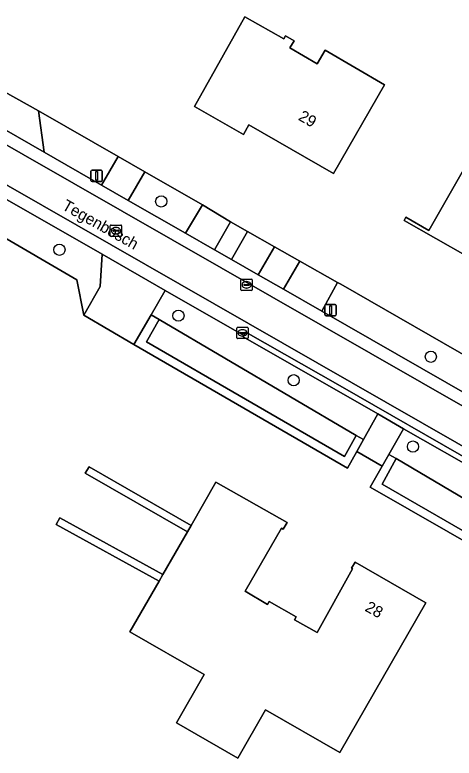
# Model space of a CAD drawing. Extents: x 156502 to 159075, y 384229 to 386100.
# Drawn here: x 157102.6 to 157141.1, y 385699.9 to 385765 of the extents above; entities that cross this region are included whole.
import ezdxf

# ---------------------------------------------------------------- set-up
doc = ezdxf.new("R2010")
doc.units = 0
for name, color, linetype in [('IMGEO_Berm_groen', 7, 'Continuous'), ('IMGEO_Berm_open', 7, 'Continuous'), ('IMGEO_Boom', 7, 'Continuous'), ('IMGEO_Brandkraan', 7, 'Continuous'), ('IMGEO_Erf', 7, 'Continuous'), ('IMGEO_Groenvoorziening', 7, 'Continuous'), ('IMGEO_Hek', 7, 'Continuous'), ('IMGEO_Kolk', 7, 'Continuous'), ('IMGEO_Lichtmast', 7, 'Continuous'), ('IMGEO_Muur', 7, 'Continuous'), ('IMGEO_Openbare_ruimte_label', 7, 'Continuous'), ('IMGEO_Pand', 7, 'Continuous'), ('IMGEO_Pand_nummerreeks', 7, 'Continuous'), ('IMGEO_Rijbaan_lokaal_gesloten', 7, 'Continuous'), ('IMGEO_Rijbaan_lokaal_halfverhard', 7, 'Continuous'), ('IMGEO_Rijbaan_lokaal_open', 7, 'Continuous'), ('IMGEO_Rioolput', 7, 'Continuous'), ('IMGEO_Voetpad_open', 7, 'Continuous')]:
    doc.layers.add(name, color=color, linetype=linetype)

msp = doc.modelspace()

# ---------------------------------------------------------------- linework, layer by layer
at = {"layer": 'IMGEO_Berm_groen'}
for points in [[(157109.515, 385753.847), (157104.7, 385756.591), (157105.201, 385752.99), (157110.239, 385750.099), (157111.678, 385752.607)], [(157114.022, 385751.264), (157112.582, 385748.755), (157117.587, 385745.884), (157119.086, 385748.362)], [(157123.015, 385746.039), (157121.522, 385746.887), (157120.125, 385744.429), (157121.61, 385743.581)], [(157127.595, 385743.439), (157125.376, 385744.699), (157123.969, 385742.234), (157126.176, 385740.973)], [(157131.197, 385741.421), (157130.921, 385741.579), (157129.529, 385739.04), (157142.675, 385731.515), (157144.11, 385733.995)], [(157122.629, 385736.809), (157122.692, 385736.917), (157115.815, 385740.863), (157114.588, 385738.742), (157115.289, 385738.328), (157132.534, 385728.173), (157133.189, 385727.815), (157134.443, 385730.048)]]:
    msp.add_lwpolyline(points, close=True, dxfattribs=at)
at = {"layer": 'IMGEO_Berm_open'}
for points in [[(157151.556, 385720.809), (157143.135, 385725.639), (157131.139, 385732.504), (157122.862, 385737.211), (157122.692, 385736.917)], [(157122.692, 385736.917), (157122.629, 385736.809), (157134.443, 385730.048), (157136.699, 385728.757), (157143.67, 385724.768), (157152.438, 385719.741)]]:
    msp.add_lwpolyline(points, dxfattribs=at)
at = {"layer": 'IMGEO_Boom'}
for centre in [(157115.464, 385748.663), (157106.548, 385744.43), (157116.973, 385738.659), (157139.084, 385735.062), (157127.07, 385733.005), (157137.513, 385727.198)]:
    msp.add_circle(centre, 0.489, dxfattribs=at)
at = {"layer": 'IMGEO_Brandkraan'}
for p, q in [((157110.997, 385745.674), (157110.997, 385746.526)), ((157111.072, 385746.6), (157111.924, 385746.6)), ((157111.256, 385746.094), (157111.256, 385746.106)), ((157111.299, 385746.143), (157111.697, 385746.143)), ((157111.485, 385746.38), (157111.51, 385746.38)), ((157111.74, 385746.106), (157111.74, 385746.094)), ((157111.998, 385746.526), (157111.998, 385745.674)), ((157111.924, 385745.6), (157111.072, 385745.6)), ((157111.694, 385746.057), (157111.296, 385746.057)), ((157111.508, 385745.82), (157111.483, 385745.82))]:
    msp.add_line(p, q, dxfattribs=at)
for points in [[(157110.997, 385745.674), (157110.997, 385746.526)], [(157111.072, 385746.6), (157111.924, 385746.6)], [(157111.998, 385746.526), (157111.998, 385745.674)], [(157111.924, 385745.6), (157111.072, 385745.6)]]:
    msp.add_lwpolyline(points, dxfattribs=at)
for centre, radius, start, end in [((157111.074, 385746.524), 0.0765, 91.55205, 178.44795), ((157111.074, 385746.524), 0.0765, 91.55205, 178.44795), ((157111.296, 385746.103), 0.0403, 85.87752, 175.75265), ((157111.293, 385746.093), 0.0366, 178.93798, 274.71019), ((157111.697, 385746.1), 0.043, 264.86636, 352.45326), ((157111.701, 385746.105), 0.0386, 1.73085, 96.63898), ((157111.922, 385746.524), 0.0765, 1.55205, 88.44795), ((157111.922, 385746.524), 0.0765, 1.55205, 88.44795), ((157111.074, 385745.676), 0.0765, 181.55205, 268.44795), ((157111.074, 385745.676), 0.0765, 181.55205, 268.44795), ((157111.922, 385745.676), 0.0765, 271.55205, 358.44795), ((157111.922, 385745.676), 0.0765, 271.55205, 358.44795)]:
    msp.add_arc(centre, radius, start, end, dxfattribs=at)
for centre, major_axis, ratio, start_param, end_param in [((157111.484, 385746.1), (-0.387, 0.002), 0.722429, 4.712389, 7.853982), ((157111.509, 385746.1), (-0.39, 0.002), 0.717154, 1.570796, 4.712389)]:
    msp.add_ellipse(centre, major_axis=major_axis, ratio=ratio, start_param=start_param, end_param=end_param, dxfattribs=at)
at = {"layer": 'IMGEO_Erf'}
for points in [[(157048.701, 385788.533), (157057.714, 385783.415), (157062.278, 385780.824), (157070.393, 385776.216), (157073.942, 385774.201), (157084.266, 385768.252), (157086.152, 385767.162), (157101.744, 385758.276), (157104.7, 385756.591), (157109.515, 385753.847), (157111.678, 385752.607), (157114.022, 385751.264), (157119.086, 385748.362), (157121.522, 385746.887), (157123.015, 385746.039), (157125.376, 385744.699), (157127.595, 385743.439), (157130.921, 385741.579), (157131.197, 385741.421), (157144.11, 385733.995)], [(157147.432, 385715.812), (157133.773, 385723.654), (157134.821, 385725.475), (157132.597, 385726.756), (157131.792, 385725.315), (157113.077, 385736.144), (157108.687, 385738.705), (157108.063, 385741.81), (157080.131, 385758.103), (157080.304, 385758.402), (157074.239, 385761.861), (157074.046, 385761.597), (157054.491, 385772.88), (157047.62, 385771.736)], [(157155.054, 385714.92), (157136.059, 385726.15), (157134.817, 385723.916), (157148.149, 385716.222)]]:
    msp.add_lwpolyline(points, dxfattribs=at)
for points in [[(157135.024, 385758.88), (157130.566, 385751.114), (157123.153, 385755.388), (157122.659, 385754.53), (157118.377, 385756.989), (157122.783, 385764.825), (157126.205, 385762.901), (157126.359, 385763.168), (157127.097, 385762.742), (157126.732, 385762.11), (157129.127, 385760.725), (157129.832, 385761.927)], [(157145.011, 385756.807), (157153.044, 385752.202), (157152.682, 385751.64), (157154.769, 385750.435), (157156.174, 385752.869), (157159.745, 385750.827), (157155.568, 385743.525), (157151.995, 385745.568), (157152.803, 385746.981), (157150.715, 385748.193), (157146.759, 385741.271), (157143.69, 385743.027), (157143.418, 385742.572), (157142.025, 385743.36), (157142.291, 385743.83), (157136.743, 385747.004), (157136.902, 385747.281), (157138.903, 385746.106)], [(157118.085, 385720.296), (157120.262, 385724.082), (157126.486, 385720.538), (157126.139, 385719.951), (157125.993, 385720.037), (157122.807, 385714.519), (157124.768, 385713.361), (157124.932, 385713.638), (157127.284, 385712.292), (157127.135, 385712.031), (157129.124, 385710.909), (157132.229, 385716.487), (157132.142, 385716.536), (157132.448, 385717.077), (157138.641, 385713.517), (157131.101, 385700.4), (157124.599, 385704.138), (157122.166, 385699.907), (157116.791, 385702.997), (157119.223, 385707.228), (157112.721, 385710.965), (157115.281, 385715.419), (157106.27, 385720.374), (157106.584, 385720.945), (157115.606, 385715.984), (157117.757, 385719.726), (157108.815, 385724.856), (157109.142, 385725.426)]]:
    msp.add_lwpolyline(points, close=True, dxfattribs=at)
at = {"layer": 'IMGEO_Groenvoorziening'}
for points in [[(157081.499, 385760.496), (157080.304, 385758.402), (157080.131, 385758.103), (157108.063, 385741.81), (157108.687, 385738.705), (157110.125, 385741.217), (157110.277, 385744.036)], [(157115.289, 385738.328), (157114.177, 385736.375), (157131.533, 385726.329), (157132.534, 385728.173)]]:
    msp.add_lwpolyline(points, close=True, dxfattribs=at)
msp.add_lwpolyline([(157152.438, 385719.741), (157143.67, 385724.768), (157136.699, 385728.757), (157135.417, 385726.51), (157136.059, 385726.15), (157155.054, 385714.92), (157165.17, 385704.25), (157165.011, 385703.658), (157167.069, 385705.548), (157167.262, 385706.33), (157166.599, 385707.057), (157163.676, 385710.253), (157162.212, 385711.565), (157160.802, 385712.985)], dxfattribs=at)
at = {"layer": 'IMGEO_Hek'}
for points in [[(157108.687, 385738.705), (157108.063, 385741.81), (157080.131, 385758.103)], [(157101.744, 385758.276), (157104.7, 385756.591)], [(157104.7, 385756.591), (157109.515, 385753.847)], [(157131.197, 385741.421), (157144.11, 385733.995)]]:
    msp.add_lwpolyline(points, dxfattribs=at)
at = {"layer": 'IMGEO_Kolk'}
for p, q in [((157122.16, 385737.652), (157123.012, 385737.652)), ((157122.085, 385736.726), (157122.085, 385737.578)), ((157122.344, 385737.146), (157122.344, 385737.158)), ((157122.782, 385737.109), (157122.384, 385737.109)), ((157122.387, 385737.195), (157122.785, 385737.195)), ((157122.573, 385737.432), (157122.598, 385737.432)), ((157122.828, 385737.158), (157122.828, 385737.146)), ((157123.086, 385737.578), (157123.086, 385736.726)), ((157123.012, 385736.652), (157122.16, 385736.652)), ((157122.596, 385736.872), (157122.571, 385736.872))]:
    msp.add_line(p, q, dxfattribs=at)
for points in [[(157122.16, 385737.652), (157123.012, 385737.652)], [(157122.085, 385736.726), (157122.085, 385737.578)], [(157123.086, 385737.578), (157123.086, 385736.726)], [(157123.012, 385736.652), (157122.16, 385736.652)]]:
    msp.add_lwpolyline(points, dxfattribs=at)
for centre, radius, start, end in [((157122.162, 385737.576), 0.0765, 91.55205, 178.44795), ((157122.162, 385737.576), 0.0765, 91.55205, 178.44795), ((157123.01, 385737.576), 0.0765, 1.55205, 88.44795), ((157123.01, 385737.576), 0.0765, 1.55205, 88.44795), ((157122.384, 385737.155), 0.0403, 85.87752, 175.75265), ((157122.381, 385737.145), 0.0366, 178.93798, 274.71019), ((157122.785, 385737.152), 0.043, 264.86636, 352.45326), ((157122.789, 385737.157), 0.0386, 1.73085, 96.63898), ((157122.162, 385736.728), 0.0765, 181.55205, 268.44795), ((157122.162, 385736.728), 0.0765, 181.55205, 268.44795), ((157123.01, 385736.728), 0.0765, 271.55205, 358.44795), ((157123.01, 385736.728), 0.0765, 271.55205, 358.44795)]:
    msp.add_arc(centre, radius, start, end, dxfattribs=at)
for centre, major_axis, ratio, start_param, end_param in [((157122.572, 385737.152), (-0.387, 0.002), 0.722429, 4.712389, 7.853982), ((157122.597, 385737.152), (-0.39, 0.002), 0.717154, 1.570796, 4.712389)]:
    msp.add_ellipse(centre, major_axis=major_axis, ratio=ratio, start_param=start_param, end_param=end_param, dxfattribs=at)
at = {"layer": 'IMGEO_Lichtmast'}
for p, q in [((157109.31, 385750.506), (157109.31, 385751.306)), ((157109.31, 385751.306), (157109.31, 385750.506)), ((157109.41, 385751.406), (157110.2, 385751.406)), ((157110.2, 385751.406), (157109.41, 385751.406)), ((157110.3, 385751.306), (157110.3, 385750.506)), ((157110.3, 385750.506), (157110.3, 385751.306)), ((157110.2, 385750.406), (157109.41, 385750.406)), ((157109.41, 385750.406), (157110.2, 385750.406)), ((157129.909, 385739.652), (157130.699, 385739.652)), ((157130.699, 385739.652), (157129.909, 385739.652)), ((157129.809, 385738.752), (157129.809, 385739.552)), ((157129.809, 385739.552), (157129.809, 385738.752)), ((157130.799, 385739.552), (157130.799, 385738.752)), ((157130.799, 385738.752), (157130.799, 385739.552)), ((157130.699, 385738.652), (157129.909, 385738.652)), ((157129.909, 385738.652), (157130.699, 385738.652))]:
    msp.add_line(p, q, dxfattribs=at)
for points in [[(157109.73, 385751.281), (157109.88, 385751.281), (157109.88, 385750.531), (157109.73, 385750.531), (157109.73, 385751.281)], [(157130.229, 385739.527), (157130.379, 385739.527), (157130.379, 385738.777), (157130.229, 385738.777), (157130.229, 385739.527)]]:
    msp.add_lwpolyline(points, dxfattribs=at)
for centre, start, end in [((157109.41, 385751.306), 90, 180), ((157109.41, 385751.306), 90, 180), ((157110.2, 385751.306), 0, 90), ((157110.2, 385751.306), 360, 90), ((157109.41, 385750.506), 180, 270), ((157109.41, 385750.506), 180, 270), ((157110.2, 385750.506), 270, 0), ((157110.2, 385750.506), 270, 0), ((157129.909, 385739.552), 90, 180), ((157129.909, 385739.552), 90, 180), ((157130.699, 385739.552), 0, 90), ((157130.699, 385739.552), 360, 90), ((157129.909, 385738.752), 180, 270), ((157129.909, 385738.752), 180, 270), ((157130.699, 385738.752), 270, 0), ((157130.699, 385738.752), 270, 0)]:
    msp.add_arc(centre, 0.1, start, end, dxfattribs=at)
at = {"layer": 'IMGEO_Muur'}
for points in [[(157133.189, 385727.815), (157132.534, 385728.173), (157131.533, 385726.329), (157114.177, 385736.375), (157115.289, 385738.328), (157114.588, 385738.742), (157113.077, 385736.144), (157131.792, 385725.315), (157132.597, 385726.756)], [(157148.362, 385711.898), (157148.149, 385716.222), (157134.817, 385723.916), (157136.059, 385726.15), (157135.417, 385726.51), (157134.821, 385725.475), (157133.773, 385723.654), (157147.432, 385715.812), (157147.812, 385707.892), (157148.558, 385707.925)], [(157118.085, 385720.296), (157109.142, 385725.426), (157108.815, 385724.856), (157117.757, 385719.726)], [(157115.606, 385715.984), (157106.584, 385720.945), (157106.27, 385720.374), (157115.281, 385715.419)]]:
    msp.add_lwpolyline(points, close=True, dxfattribs=at)
at = {"layer": 'IMGEO_Pand'}
for points in [[(157130.566, 385751.114), (157135.024, 385758.88), (157129.832, 385761.927), (157129.127, 385760.725), (157126.732, 385762.11), (157127.097, 385762.742), (157126.359, 385763.168), (157126.205, 385762.901), (157122.783, 385764.825), (157118.377, 385756.989), (157122.659, 385754.53), (157123.153, 385755.388)], [(157146.759, 385741.271), (157150.715, 385748.193), (157152.803, 385746.981), (157151.995, 385745.568), (157155.568, 385743.525), (157159.745, 385750.827), (157156.174, 385752.869), (157154.769, 385750.435), (157152.682, 385751.64), (157153.044, 385752.202), (157145.011, 385756.807), (157138.903, 385746.106), (157136.902, 385747.281), (157136.743, 385747.004), (157142.291, 385743.83), (157142.025, 385743.36), (157143.418, 385742.572), (157143.69, 385743.027)], [(157115.606, 385715.984), (157115.281, 385715.419), (157112.721, 385710.965), (157119.223, 385707.228), (157116.791, 385702.997), (157122.166, 385699.907), (157124.599, 385704.138), (157131.101, 385700.4), (157138.641, 385713.517), (157132.448, 385717.077), (157132.142, 385716.536), (157132.229, 385716.487), (157129.124, 385710.909), (157127.135, 385712.031), (157127.284, 385712.292), (157124.932, 385713.638), (157124.768, 385713.361), (157122.807, 385714.519), (157125.993, 385720.037), (157126.139, 385719.951), (157126.486, 385720.538), (157120.262, 385724.082), (157118.085, 385720.296), (157117.757, 385719.726)]]:
    msp.add_lwpolyline(points, close=True, dxfattribs=at)
at = {"layer": 'IMGEO_Rijbaan_lokaal_gesloten'}
for points in [[(157155.604, 385722.866), (157042.417, 385787.656)], [(157047.474, 385781.289), (157153.385, 385720.619)]]:
    msp.add_lwpolyline(points, dxfattribs=at)
at = {"layer": 'IMGEO_Rijbaan_lokaal_halfverhard'}
for points in [[(157156.009, 385723.887), (157148.433, 385728.196), (157142.675, 385731.515), (157129.529, 385739.04), (157126.176, 385740.973), (157123.969, 385742.234), (157121.61, 385743.581), (157120.125, 385744.429), (157117.587, 385745.884), (157112.582, 385748.755), (157110.239, 385750.099), (157105.201, 385752.99), (157098.368, 385756.889), (157083.861, 385765.187), (157082.83, 385765.787), (157073.474, 385771.108), (157068.127, 385774.18), (157061.801, 385777.83), (157055.407, 385781.512), (157048.506, 385785.444), (157044.158, 385787.921)], [(157042.417, 385787.656), (157155.604, 385722.866)], [(157047.474, 385781.289), (157047.846, 385779.743), (157048.686, 385779.263), (157061.322, 385772.036), (157075.399, 385763.984), (157081.499, 385760.496), (157110.277, 385744.036), (157115.815, 385740.863), (157122.692, 385736.917), (157122.862, 385737.211), (157131.139, 385732.504), (157143.135, 385725.639), (157151.556, 385720.809)], [(157153.385, 385720.619), (157047.474, 385781.289)]]:
    msp.add_lwpolyline(points, dxfattribs=at)
at = {"layer": 'IMGEO_Rijbaan_lokaal_open'}
for points in [[(157104.7, 385756.591), (157101.744, 385758.276), (157098.368, 385756.889), (157105.201, 385752.99)], [(157114.022, 385751.264), (157111.678, 385752.607), (157110.239, 385750.099), (157112.582, 385748.755)], [(157117.587, 385745.884), (157120.125, 385744.429), (157121.522, 385746.887), (157119.086, 385748.362)], [(157125.376, 385744.699), (157123.015, 385746.039), (157121.61, 385743.581), (157123.969, 385742.234)], [(157115.815, 385740.863), (157110.277, 385744.036), (157110.125, 385741.217), (157108.687, 385738.705), (157113.077, 385736.144), (157114.588, 385738.742)], [(157129.529, 385739.04), (157130.921, 385741.579), (157127.595, 385743.439), (157126.176, 385740.973)]]:
    msp.add_lwpolyline(points, close=True, dxfattribs=at)
at = {"layer": 'IMGEO_Rioolput'}
for p, q in [((157122.444, 385740.933), (157122.444, 385741.785)), ((157122.519, 385741.859), (157123.371, 385741.859)), ((157122.932, 385741.639), (157122.957, 385741.639)), ((157123.445, 385741.785), (157123.445, 385740.933)), ((157122.703, 385741.353), (157122.703, 385741.365)), ((157123.141, 385741.316), (157122.743, 385741.316)), ((157122.746, 385741.402), (157123.144, 385741.402)), ((157122.955, 385741.079), (157122.93, 385741.079)), ((157123.187, 385741.365), (157123.187, 385741.353)), ((157123.371, 385740.859), (157122.519, 385740.859))]:
    msp.add_line(p, q, dxfattribs=at)
for points in [[(157122.444, 385740.933), (157122.444, 385741.785)], [(157122.519, 385741.859), (157123.371, 385741.859)], [(157123.445, 385741.785), (157123.445, 385740.933)], [(157123.371, 385740.859), (157122.519, 385740.859)]]:
    msp.add_lwpolyline(points, dxfattribs=at)
for centre, radius, start, end in [((157122.521, 385741.783), 0.0765, 91.55205, 178.44795), ((157122.521, 385741.783), 0.0765, 91.55205, 178.44795), ((157123.369, 385741.783), 0.0765, 1.55205, 88.44795), ((157123.369, 385741.783), 0.0765, 1.55205, 88.44795), ((157122.521, 385740.935), 0.0765, 181.55205, 268.44795), ((157122.521, 385740.935), 0.0765, 181.55205, 268.44795), ((157122.743, 385741.362), 0.0403, 85.87752, 175.75265), ((157122.74, 385741.352), 0.0366, 178.93798, 274.71019), ((157123.144, 385741.359), 0.043, 264.86636, 352.45326), ((157123.148, 385741.364), 0.0386, 1.73085, 96.63898), ((157123.369, 385740.935), 0.0765, 271.55205, 358.44795), ((157123.369, 385740.935), 0.0765, 271.55205, 358.44795)]:
    msp.add_arc(centre, radius, start, end, dxfattribs=at)
for centre, major_axis, ratio, start_param, end_param in [((157122.931, 385741.359), (-0.387, 0.002), 0.722429, 4.712389, 7.853982), ((157122.956, 385741.359), (-0.39, 0.002), 0.717154, 1.570796, 4.712389)]:
    msp.add_ellipse(centre, major_axis=major_axis, ratio=ratio, start_param=start_param, end_param=end_param, dxfattribs=at)
at = {"layer": 'IMGEO_Voetpad_open'}
msp.add_lwpolyline([(157136.699, 385728.757), (157134.443, 385730.048), (157133.189, 385727.815), (157132.597, 385726.756), (157134.821, 385725.475), (157135.417, 385726.51)], close=True, dxfattribs=at)

# ---------------------------------------------------------------- texts
at = {"layer": 'IMGEO_Openbare_ruimte_label'}
msp.add_text('Tegenbosch', height=1, rotation=330.58918, dxfattribs=at).set_placement((157106.697, 385748.018))
at = {"layer": 'IMGEO_Pand_nummerreeks'}
for s, rotation, p in [('29', 330.03421, (157127.402, 385755.847)), ('28', 331.07357, (157133.237, 385712.846))]:
    msp.add_text(s, height=1, rotation=rotation, dxfattribs=at).set_placement(p)

doc.saveas('drawing.dxf')
